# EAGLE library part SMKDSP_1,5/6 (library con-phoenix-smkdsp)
Printklemme, Nennstrom: 17,5 A, Bemessungsspannung: 250 V, Raster: 5,0 mm Source: http://eshop.phoenixcontact.de .. 1733415.pdf
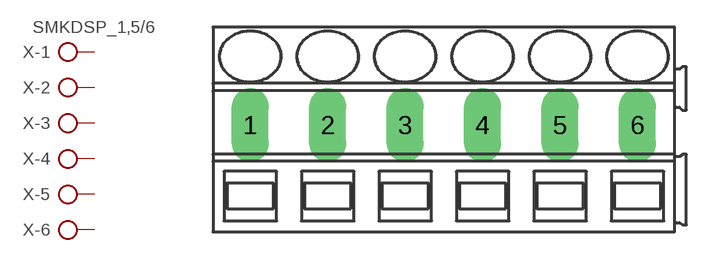
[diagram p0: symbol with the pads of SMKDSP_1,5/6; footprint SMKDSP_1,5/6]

Designator prefix X; gates -1=KLV -2=KL -3=KL -4=KL -5=KL -6=KL

## SMKDSP_1,5/6 (MF: FARNELL; MPN: 1733619; OC_FARNELL: 3041270; OC_NEWARK: 71C4132)  [SMKDSP_1,5/6]
1  -1:KL  pas
2  -2:KL  pas
3  -3:KL  pas
4  -4:KL  pas
5  -5:KL  pas
6  -6:KL  pas

## Footprint SMKDSP_1,5/6 (pad centres in mm)
Printklemme, Nennstrom: 17,5 A, Bemessungsspannung: 250 V, Raster: 5,0 mm Source: http://eshop.phoenixcontact.de .. 1733415.pdf
drill 1.6 pad 1.8 long: 1 -2.5,0; 2 2.5,0; 3 7.5,0; 4 12.5,0; 5 17.5,0; 6 22.5,0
